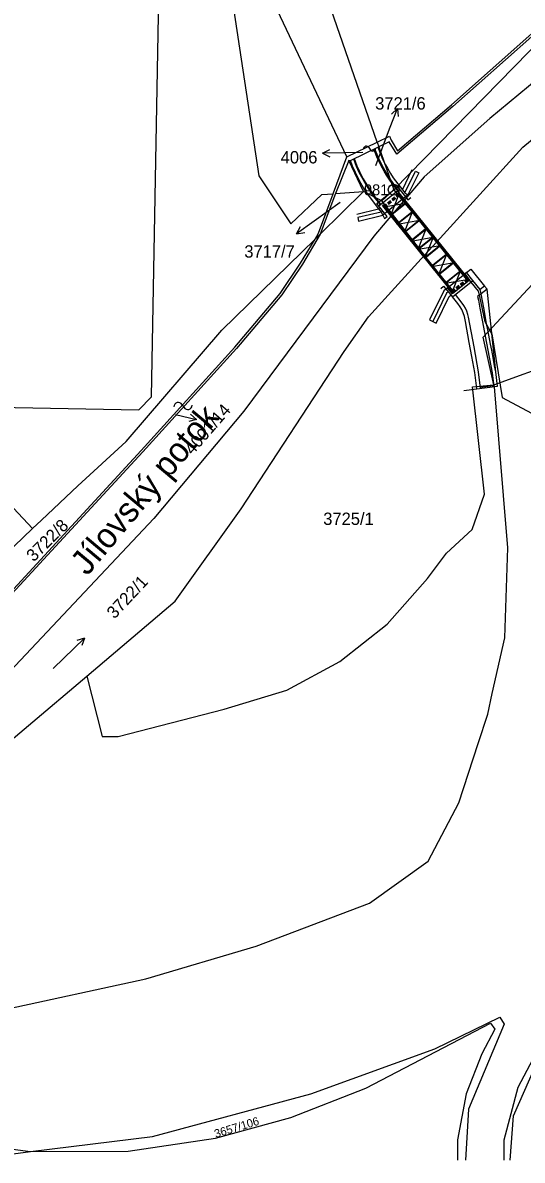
# Model space of a CAD drawing. Extents: x -747779 to -747197, y -965543 to -964919.
# Drawn here: x -747670.2 to -747601.4, y -965537.7 to -965381 of the extents above; entities that cross this region are included whole.
import ezdxf

# ---------------------------------------------------------------- set-up
doc = ezdxf.new("R2010")
doc.units = 0
for name, color, linetype in [('Hranice parcel', 7, 'Continuous'), ('Parcelní čísla', 7, 'Continuous'), ('Pop  PČ popisy', 7, 'Continuous'), ('projekt lávka pro pěší', 7, 'Continuous'), ('stávající trasa metropol sítě', 7, 'Continuous'), ('Vnitřní kresba', 7, 'Continuous'), ('Značky bodu BP', 7, 'Continuous'), ('Značky budov', 7, 'Continuous'), ('Značky kultur', 7, 'Continuous')]:
    doc.layers.add(name, color=color, linetype=linetype)

msp = doc.modelspace()

# ---------------------------------------------------------------- linework, layer by layer
at = {"layer": 'Hranice parcel'}
for p, q in [((-747625.57, -965399.47), (-747643.98, -965360.59)), ((-747625.57, -965399.47), (-747621.4, -965397.45)), ((-747621.4, -965397.45), (-747621.17, -965398.11)), ((-747621.17, -965398.11), (-747619.13, -965404.01)), ((-747623.3, -965404.27), (-747625.33, -965399.98)), ((-747623.3, -965404.27), (-747629.27, -965410.12)), ((-747629.27, -965410.12), (-747629.97, -965410.8))]:
    msp.add_line(p, q, dxfattribs=at)
for points in [[(-747661.4, -965470.99), (-747649.22, -965460.69), (-747640.13, -965447.94), (-747625.94, -965426.31), (-747622.59, -965421.5), (-747614.88, -965413.02), (-747613.22, -965411.19), (-747601.34, -965398.13), (-747565.97, -965368.89), (-747549.19, -965343.06), (-747542.01, -965330.04), (-747531.93, -965300.92), (-747529.16, -965300.36), (-747523.38, -965299.2)], [(-747621.4, -965397.45), (-747634.43, -965359.81), (-747642.96, -965324.94), (-747647.24, -965306.07)], [(-747621.4, -965397.45), (-747619.73, -965396.64), (-747619.47, -965397.18), (-747618.61, -965398.65), (-747611.16, -965392.29), (-747589.47, -965372.96), (-747577.69, -965359.27), (-747565.25, -965341.77), (-747552.46, -965316.97)], [(-747553.47, -965319.72), (-747565.02, -965342.13), (-747577.45, -965359.48), (-747589.24, -965373.2), (-747610.98, -965392.52), (-747618.69, -965399.11), (-747619.74, -965397.42), (-747621.17, -965398.11)], [(-747553.47, -965319.72), (-747559.26, -965335.45), (-747575.7, -965359.57), (-747619.13, -965404.01)], [(-747605.34, -965430.88), (-747606.8, -965424.33), (-747588.95, -965405.12), (-747564.08, -965380.49), (-747548.91, -965365.21)], [(-747621.17, -965398.11), (-747625.14, -965400.01), (-747625.33, -965399.98)], [(-747629.97, -965410.8), (-747629.49, -965410), (-747627.49, -965404.55), (-747627.44, -965404.41), (-747625.57, -965399.47)], [(-747625.33, -965399.98), (-747627.16, -965404.51), (-747627.17, -965404.53), (-747629.27, -965410.12)], [(-747619.13, -965404.01), (-747620.76, -965405.54), (-747623.3, -965404.27)], [(-747629.27, -965410.12), (-747631.7, -965414.28), (-747634.55, -965418.49), (-747640.77, -965425.89), (-747653.68, -965440.12), (-747676.11, -965464.41), (-747681.84, -965470.18), (-747689.91, -965478.08), (-747692.06, -965477.11)], [(-747691.74, -965476.88), (-747689.97, -965477.72), (-747682.05, -965470.01), (-747676.31, -965464.21), (-747653.9, -965439.92), (-747641, -965425.7), (-747634.78, -965418.31), (-747631.96, -965414.13), (-747629.97, -965410.8)], [(-747668.87, -965450.69), (-747667.64, -965449.54), (-747662.61, -965444.8), (-747655.99, -965438.68), (-747642.81, -965423.37), (-747629.97, -965410.8)], [(-747605.34, -965430.88), (-747596.5, -965427.67), (-747592.97, -965420.87), (-747587.62, -965413.9), (-747581.5, -965418.47)], [(-747736.34, -965519.7), (-747732.55, -965519.88), (-747710.49, -965519.81), (-747692.88, -965519.37), (-747673.14, -965517.04), (-747653.27, -965512.7), (-747638.07, -965508.19), (-747622.48, -965502.29), (-747614.4, -965496.49), (-747610.15, -965488.46), (-747607.5, -965480.29), (-747606.19, -965476.23), (-747605.56, -965473.4), (-747603.85, -965465.74), (-747603.43, -965453.35), (-747605.28, -965431.15), (-747605.34, -965430.88)], [(-747661.4, -965470.99), (-747659.26, -965479.31), (-747657.06, -965479.34), (-747642.47, -965475.55), (-747633.85, -965472.95), (-747626.56, -965468.97), (-747620.05, -965463.87), (-747614.5, -965457.57), (-747611.88, -965454.06), (-747608.35, -965450.82), (-747606.65, -965445.93), (-747608.28, -965431.16), (-747605.34, -965430.88)], [(-747676.6, -965448.05), (-747676, -965448.13), (-747673.52, -965445.77), (-747668.87, -965450.69)], [(-747689.84, -965475.54), (-747684.31, -965470.11), (-747671.42, -965453.1), (-747668.87, -965450.69)], [(-747717.91, -965506.29), (-747712.29, -965505), (-747702.68, -965501.08), (-747684.71, -965490.18), (-747677.49, -965484.61), (-747661.4, -965470.99)], [(-747603.92, -965537.69), (-747603.92, -965534.88), (-747602.02, -965527.63), (-747598.68, -965521.38), (-747593.63, -965515.5), (-747588.06, -965510.88), (-747579.86, -965505.84), (-747563.56, -965497.92), (-747541.94, -965487.88)], [(-747603.1, -965537.69), (-747602.65, -965531.59), (-747598.33, -965521.78), (-747593.66, -965516.49), (-747584.11, -965509.72), (-747561.67, -965499.21), (-747542.43, -965490.52)], [(-747669.17, -965536.51), (-747652.37, -965534.41), (-747630.57, -965528.53), (-747613.46, -965522.35), (-747604.52, -965517.99), (-747603.92, -965518.95), (-747608.84, -965530.65), (-747609.26, -965537.69)], [(-747669.17, -965536.51), (-747655.68, -965536.42), (-747643.67, -965534.63), (-747633.29, -965531.82), (-747622.96, -965527.76), (-747605.81, -965518.82), (-747605.22, -965519.62), (-747606.99, -965523.02), (-747609.18, -965528.55), (-747610.35, -965534.89), (-747610.37, -965537.69)], [(-747692.46, -965532.2), (-747680.3, -965535.03), (-747669.17, -965536.51)], [(-747675.99, -965537.16), (-747672.22, -965536.89), (-747669.17, -965536.51)]]:
    msp.add_lwpolyline(points, dxfattribs=at)
at = {"layer": 'Pop  PČ popisy'}
for p, q in [((-747619.7, -965395.63), (-747618.62, -965392.83)), ((-747618.62, -965392.83), (-747619.45, -965393.58)), ((-747618.62, -965392.83), (-747618.52, -965393.94)), ((-747621.59, -965400.69), (-747619.7, -965395.63)), ((-747628.94, -965398.97), (-747627.95, -965398.45)), ((-747625.94, -965398.92), (-747628.94, -965398.97)), ((-747628.94, -965398.97), (-747627.93, -965399.46)), ((-747623.41, -965398.88), (-747625.94, -965398.92)), ((-747626.53, -965405.75), (-747630.07, -965408.32)), ((-747630.07, -965408.32), (-747632.5, -965410.08)), ((-747632.5, -965410.08), (-747631.98, -965409.09)), ((-747632.5, -965410.08), (-747631.39, -965409.9)), ((-747649.2, -965434.98), (-747646.28, -965435.66)), ((-747646.28, -965435.66), (-747647.14, -965434.94)), ((-747646.28, -965435.66), (-747647.36, -965435.92))]:
    msp.add_line(p, q, dxfattribs=at)
at = {"layer": 'projekt lávka pro pěší'}
for p, q in [((-747617.94, -965404), (-747616.6, -965401.24)), ((-747621.17, -965406.21), (-747618.36, -965403.92)), ((-747620, -965405.8), (-747619.59, -965405.48)), ((-747619.95, -965405.85), (-747619.55, -965405.53)), ((-747619.54, -965407.51), (-747618.41, -965404.69)), ((-747619.41, -965405.32), (-747619.01, -965405)), ((-747619.37, -965405.38), (-747618.97, -965405.06)), ((-747619.31, -965405.46), (-747618.9, -965405.13)), ((-747619.26, -965405.51), (-747618.86, -965405.19)), ((-747618.82, -965404.86), (-747618.41, -965404.53)), ((-747618.78, -965404.91), (-747618.48, -965404.68)), ((-747618.72, -965404.99), (-747618.42, -965404.76)), ((-747618.67, -965405.05), (-747618.26, -965404.72)), ((-747608.88, -965416.61), (-747618.62, -965404.51)), ((-747608.78, -965416.62), (-747618.61, -965404.41)), ((-747620.86, -965407.08), (-747620.64, -965406.89)), ((-747610.84, -965418.28), (-747620.67, -965406.08)), ((-747620.59, -965406.28), (-747620.19, -965405.95)), ((-747610.83, -965418.18), (-747620.57, -965406.08)), ((-747620.51, -965406.37), (-747617.48, -965405.85)), ((-747620.44, -965406.25), (-747620.14, -965406.01)), ((-747620.44, -965406.47), (-747620.03, -965406.15)), ((-747620.39, -965406.33), (-747620.08, -965406.08)), ((-747619.89, -965405.93), (-747619.49, -965405.61)), ((-747619.84, -965405.99), (-747619.44, -965405.67)), ((-747617.65, -965409.86), (-747616.53, -965407.04)), ((-747618.63, -965408.73), (-747615.6, -965408.2)), ((-747615.78, -965412.2), (-747614.65, -965409.38)), ((-747616.75, -965411.07), (-747613.73, -965410.54)), ((-747615.78, -965412.2), (-747612.75, -965411.67)), ((-747614.81, -965413.34), (-747613.68, -965410.52)), ((-747612.94, -965415.7), (-747611.81, -965412.87)), ((-747613.91, -965414.56), (-747610.88, -965414.03)), ((-747612.04, -965416.88), (-747609.01, -965416.35)), ((-747611.06, -965418.01), (-747609.94, -965415.19)), ((-747609.41, -965416.54), (-747609.01, -965416.21)), ((-747609.36, -965416.6), (-747609.05, -965416.34)), ((-747609.3, -965416.68), (-747609.01, -965416.44)), ((-747609.25, -965416.74), (-747608.85, -965416.4)), ((-747611.18, -965417.96), (-747610.78, -965417.64)), ((-747611.03, -965418.15), (-747610.62, -965417.83)), ((-747611.01, -965417.92), (-747610.73, -965417.7)), ((-747610.95, -965417.99), (-747610.67, -965417.77)), ((-747610.59, -965417.49), (-747610.19, -965417.17)), ((-747610.54, -965417.54), (-747610.14, -965417.22)), ((-747610.48, -965417.62), (-747610.08, -965417.3)), ((-747610.44, -965417.68), (-747610.03, -965417.36)), ((-747610, -965417.01), (-747609.6, -965416.69)), ((-747609.96, -965417.07), (-747609.55, -965416.75)), ((-747609.9, -965417.15), (-747609.49, -965416.82)), ((-747609.85, -965417.2), (-747609.45, -965416.88)), ((-747606.63, -965417.27), (-747606.27, -965417.68)), ((-747605.38, -965431.02), (-747607.17, -965431.25))]:
    msp.add_line(p, q, dxfattribs=at)
for points in [[(-747618.62, -965404.11), (-747619.59, -965402.83), (-747620.14, -965402), (-747620.46, -965401.46), (-747620.88, -965400.71), (-747621.35, -965399.71), (-747621.88, -965398.42)], [(-747618.52, -965404.07), (-747619.5, -965402.79), (-747620.04, -965401.96), (-747620.36, -965401.41), (-747620.78, -965400.67), (-747621.25, -965399.67), (-747621.78, -965398.38)], [(-747621.33, -965398.16), (-747620.67, -965399.8), (-747620.53, -965400.08), (-747620.27, -965400.58), (-747620.01, -965401.05), (-747619.59, -965401.78), (-747619.19, -965402.35), (-747618.59, -965403.18), (-747617.94, -965404), (-747617.59, -965404.44), (-747617.2, -965404.73), (-747617.5, -965404.98)], [(-747625.14, -965399.95), (-747624.84, -965400.72), (-747624.46, -965401.58), (-747624.16, -965402.2), (-747623.7, -965403.06), (-747623.14, -965404.01), (-747622.73, -965404.63), (-747622.24, -965405.31), (-747621.21, -965406.62), (-747620.86, -965407.08), (-747620.63, -965407.51), (-747620.4, -965407.99), (-747620.02, -965407.68), (-747621.46, -965405.88), (-747618.61, -965403.6), (-747617.5, -965404.98), (-747620.63, -965407.51)], [(-747624.68, -965399.77), (-747624.29, -965400.78), (-747623.92, -965401.57), (-747623.4, -965402.56), (-747622.94, -965403.39), (-747621.95, -965404.87), (-747621.28, -965405.74), (-747621.03, -965406.06)], [(-747624.6, -965399.7), (-747624.21, -965400.71), (-747623.84, -965401.51), (-747623.33, -965402.49), (-747622.86, -965403.33), (-747621.88, -965404.81), (-747621.21, -965405.68), (-747620.95, -965406)], [(-747617.59, -965404.44), (-747616.13, -965401.44), (-747615.7, -965401.66), (-747617.2, -965404.73)], [(-747617.5, -965404.98), (-747617.17, -965405.39), (-747616.79, -965405.08)], [(-747624.2, -965407.35), (-747621.21, -965406.62), (-747620.99, -965406.44)], [(-747620.86, -965407.08), (-747624.1, -965407.85), (-747623.97, -965408.34), (-747620.63, -965407.51)], [(-747612.64, -965417.62), (-747612.27, -965417.31), (-747611.05, -965418.77), (-747608.25, -965416.49), (-747609.1, -965415.41), (-747608.5, -965414.93), (-747606.63, -965417.27), (-747607.22, -965417.76), (-747608.25, -965416.49)], [(-747609.1, -965415.41), (-747609.35, -965415.6), (-747608.69, -965416.45), (-747611.05, -965418.36), (-747611.71, -965417.52), (-747609.35, -965415.6)], [(-747611.71, -965417.52), (-747612.24, -965417.93), (-747614.19, -965421.94), (-747613.74, -965422.17), (-747613.29, -965422.37), (-747611.52, -965418.71), (-747611.28, -965418.51)], [(-747611.64, -965418.08), (-747611.86, -965418.27), (-747613.74, -965422.17)], [(-747609.5, -965431.64), (-747604.84, -965431.05), (-747605.07, -965429.07), (-747605.24, -965428.25), (-747605.4, -965427.38), (-747605.64, -965426.1), (-747605.79, -965425.29), (-747606.16, -965423.32), (-747606.34, -965422.41), (-747606.73, -965420.26), (-747607.09, -965418.36), (-747607.22, -965417.76)], [(-747605.07, -965429.07), (-747605.69, -965423.33), (-747606.27, -965417.68), (-747607.09, -965418.36), (-747607.58, -965418.73), (-747607.47, -965419.22), (-747607.29, -965420.32), (-747606.96, -965421.97), (-747606.36, -965425.13), (-747605.6, -965429.21), (-747605.5, -965429.96), (-747605.36, -965431.1)], [(-747607.71, -965431.39), (-747607.96, -965429.2), (-747608.38, -965427), (-747608.73, -965425.07), (-747609.27, -965422.15), (-747609.4, -965421.49), (-747609.56, -965420.95), (-747609.76, -965420.52), (-747609.98, -965420.14), (-747610.32, -965419.69), (-747611.05, -965418.77)], [(-747607.17, -965431.33), (-747607.45, -965429.08), (-747608.08, -965425.63), (-747608.84, -965421.58), (-747608.93, -965421.18), (-747609.09, -965420.74), (-747609.27, -965420.34), (-747609.47, -965419.97), (-747609.85, -965419.43), (-747610.65, -965418.45)]]:
    msp.add_lwpolyline(points, dxfattribs=at)
for points in [[(-747618.59, -965404.56), (-747618.47, -965404.47), (-747608.81, -965416.47), (-747608.92, -965416.56)], [(-747620.65, -965406.22), (-747620.54, -965406.13), (-747610.87, -965418.13), (-747610.98, -965418.22)], [(-747619.63, -965407.52), (-747617.4, -965405.73), (-747617.34, -965405.81), (-747619.57, -965407.6)], [(-747618.7, -965408.7), (-747616.45, -965406.89), (-747616.38, -965406.97), (-747618.64, -965408.78)], [(-747617.76, -965409.88), (-747615.51, -965408.06), (-747615.45, -965408.13), (-747617.7, -965409.94)], [(-747616.82, -965411.04), (-747614.56, -965409.23), (-747614.5, -965409.31), (-747616.75, -965411.12)], [(-747615.88, -965412.21), (-747613.62, -965410.4), (-747613.56, -965410.48), (-747615.81, -965412.29)], [(-747614.93, -965413.37), (-747612.67, -965411.56), (-747612.61, -965411.64), (-747614.86, -965413.46)], [(-747614, -965414.55), (-747611.74, -965412.74), (-747611.68, -965412.82), (-747613.93, -965414.63)], [(-747613.05, -965415.71), (-747610.79, -965413.9), (-747610.73, -965413.98), (-747612.98, -965415.79)], [(-747612.11, -965416.89), (-747609.86, -965415.07), (-747609.79, -965415.15), (-747612.05, -965416.97)]]:
    msp.add_lwpolyline(points, close=True, dxfattribs=at)
at = {"layer": 'stávající trasa metropol sítě'}
for points in [[(-747605.61, -965423.84), (-747606.54, -965422.2), (-747607.26, -965418.71), (-747607.46, -965417.99), (-747608.49, -965416.75), (-747618.59, -965404.2), (-747618.81, -965403.63), (-747618.96, -965403.43), (-747619.55, -965402.63), (-747620.1, -965401.77), (-747620.67, -965400.78), (-747621.23, -965399.6), (-747621.73, -965398.39)], [(-747605.61, -965423.84), (-747604.2, -965432.62), (-747599.49, -965435.14), (-747588.8, -965438.78), (-747585.09, -965439.32)]]:
    msp.add_lwpolyline(points, dxfattribs=at)
at = {"layer": 'Vnitřní kresba'}
for p, q in [((-747643.98, -965360.59), (-747637.7, -965402.11)), ((-747652.51, -965432.54), (-747651.31, -965368.01)), ((-747596.28, -965386.2), (-747605.92, -965394.18)), ((-747605.92, -965394.18), (-747614.95, -965402.23)), ((-747637.7, -965402.11), (-747633.3, -965408.68)), ((-747614.95, -965402.23), (-747617.82, -965405.61)), ((-747619.13, -965404.01), (-747617.82, -965405.61)), ((-747633.3, -965408.68), (-747629.04, -965404.65)), ((-747629.04, -965404.65), (-747627.49, -965404.55)), ((-747627.17, -965404.53), (-747623.3, -965404.27)), ((-747619.32, -965407.38), (-747620.76, -965405.54)), ((-747617.82, -965405.61), (-747619.32, -965407.38)), ((-747617.82, -965405.61), (-747613.22, -965411.19)), ((-747619.32, -965407.38), (-747621.89, -965410.41)), ((-747614.88, -965413.02), (-747619.32, -965407.38)), ((-747621.89, -965410.41), (-747639.77, -965434.53)), ((-747750.99, -965432.43), (-747654.25, -965434.32)), ((-747654.25, -965434.32), (-747652.51, -965432.54)), ((-747639.77, -965434.53), (-747652.17, -965449.3)), ((-747652.17, -965449.3), (-747672.75, -965471.13))]:
    msp.add_line(p, q, dxfattribs=at)
at = {"layer": 'Značky bodu BP'}
for radius in [0.75, 0.03]:
    msp.add_circle((-747619.13, -965404.01), radius, dxfattribs=at)
at = {"layer": 'Značky budov'}
for p, q in [((-747622.57, -965398.21), (-747622.37, -965398.47)), ((-747648.3, -965433.6), (-747648, -965434))]:
    msp.add_line(p, q, dxfattribs=at)
for centre, radius, start, end in [((-747622.91, -965398.4), 0.394, 29.2914, 181.2189), ((-747622.03, -965398.28), 0.394, 209.2914, 1.2189), ((-747648.81, -965433.89), 0.588, 29.2914, 181.2189), ((-747647.49, -965433.71), 0.588, 209.2914, 1.2189)]:
    msp.add_arc(centre, radius, start, end, dxfattribs=at)
at = {"layer": 'Značky kultur'}
for p, q in [((-747666.04, -965469.94), (-747661.72, -965465.77)), ((-747661.72, -965465.77), (-747662.78, -965466.09)), ((-747661.72, -965465.77), (-747662.08, -965466.81))]:
    msp.add_line(p, q, dxfattribs=at)

# ---------------------------------------------------------------- texts
at = {"layer": 'Parcelní čísla'}
for s, p in [('3721/6', (-747621.69, -965392.96)), ('4006', (-747634.7, -965400.38)), ('3717/7', (-747639.71, -965413.36)), ('3725/1', (-747628.84, -965450.18))]:
    msp.add_text(s, height=1.7, dxfattribs=at).set_placement(p)
for s, height, rotation, p in [('4001/14', 1.7, 49, (-747646.84, -965440.64)), ('3722/8', 1.7, 45, (-747668.7, -965455.34)), ('3722/1', 1.7, 47, (-747657.58, -965463.21)), ('3657/106', 1.139, 17, (-747643.64, -965534.63))]:
    msp.add_text(s, height=height, rotation=rotation, dxfattribs=at).set_placement(p)
at = {"layer": 'Pop  PČ popisy'}
msp.add_text('Jílovský potok', height=3.4, rotation=50, dxfattribs=at).set_placement((-747661.34, -965457.31))
at = {"layer": 'Značky bodu BP'}
msp.add_text('981', height=1.5, dxfattribs=at).set_placement((-747623.23, -965404.76))

doc.saveas('drawing.dxf')
